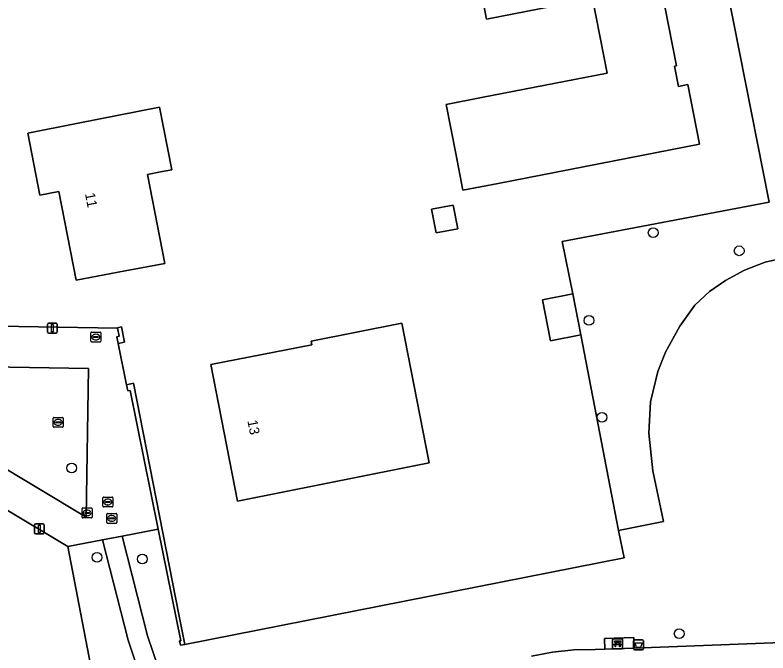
# Model space of a CAD drawing. Extents: x 157648 to 158502, y 379212 to 380938.
# Drawn here: x 158181.3 to 158256.8, y 380118.2 to 380182.1 of the extents above; entities that cross this region are included whole.
import ezdxf

# ---------------------------------------------------------------- set-up
doc = ezdxf.new("R2010")
doc.units = 0
for name, color, linetype in [('IMGEO_Afvalbak', 7, 'Continuous'), ('IMGEO_Bank', 7, 'Continuous'), ('IMGEO_Boom', 7, 'Continuous'), ('IMGEO_Brandkraan', 7, 'Continuous'), ('IMGEO_Erf', 7, 'Continuous'), ('IMGEO_Groenvoorziening', 7, 'Continuous'), ('IMGEO_Hek', 7, 'Continuous'), ('IMGEO_Kolk', 7, 'Continuous'), ('IMGEO_Lichtmast', 7, 'Continuous'), ('IMGEO_Muur', 7, 'Continuous'), ('IMGEO_Pand', 7, 'Continuous'), ('IMGEO_Pand_nummerreeks', 7, 'Continuous'), ('IMGEO_Rioolput', 7, 'Continuous'), ('IMGEO_Voetpad_halfverhard', 7, 'Continuous'), ('IMGEO_Voetpad_open', 7, 'Continuous')]:
    doc.layers.add(name, color=color, linetype=linetype)

msp = doc.modelspace()

# ---------------------------------------------------------------- linework, layer by layer
at = {"layer": 'IMGEO_Afvalbak'}
for p, q in [((158243.348, 380118.59), (158243.348, 380119.39)), ((158243.348, 380119.39), (158243.348, 380118.59)), ((158243.448, 380119.49), (158244.238, 380119.49)), ((158244.238, 380119.49), (158243.448, 380119.49)), ((158244.338, 380119.39), (158244.338, 380118.59)), ((158244.338, 380118.59), (158244.338, 380119.39)), ((158244.238, 380118.49), (158243.448, 380118.49)), ((158243.448, 380118.49), (158244.238, 380118.49))]:
    msp.add_line(p, q, dxfattribs=at)
msp.add_lwpolyline([(158243.491, 380119.204), (158244.195, 380119.204), (158244.046, 380118.734), (158243.64, 380118.734), (158243.491, 380119.204)], dxfattribs=at)
for centre, start, end in [((158243.448, 380119.39), 90, 180), ((158243.448, 380119.39), 90, 180), ((158244.238, 380119.39), 0, 90), ((158244.238, 380119.39), 360, 90), ((158243.448, 380118.59), 180, 270), ((158243.448, 380118.59), 180, 270), ((158244.238, 380118.59), 270, 0), ((158244.238, 380118.59), 270, 0)]:
    msp.add_arc(centre, 0.1, start, end, dxfattribs=at)
at = {"layer": 'IMGEO_Bank'}
for p, q in [((158241.312, 380119.603), (158242.153, 380119.603)), ((158242.153, 380119.603), (158241.312, 380119.603)), ((158241.237, 380118.678), (158241.237, 380119.519)), ((158241.237, 380119.519), (158241.237, 380118.678)), ((158241.934, 380119.001), (158241.541, 380119.001)), ((158241.546, 380119.109), (158241.546, 380119.215)), ((158241.59, 380119.215), (158241.59, 380119.109)), ((158241.878, 380119.221), (158241.596, 380119.221)), ((158241.596, 380119.103), (158241.878, 380119.103)), ((158241.884, 380119.109), (158241.884, 380119.215)), ((158241.928, 380119.215), (158241.928, 380119.109)), ((158242.237, 380119.528), (158242.237, 380118.687)), ((158242.237, 380118.687), (158242.237, 380119.528)), ((158242.162, 380118.603), (158241.321, 380118.603)), ((158241.321, 380118.603), (158242.162, 380118.603))]:
    msp.add_line(p, q, dxfattribs=at)
for points in [[(158241.484, 380119.001), (158241.342, 380119.001), (158241.454, 380119.103), (158241.54, 380119.103)], [(158241.54, 380119.221), (158241.454, 380119.221), (158241.454, 380119.382), (158242.017, 380119.382), (158242.017, 380119.221), (158241.934, 380119.221)], [(158241.534, 380118.994), (158241.534, 380118.787), (158241.491, 380118.787), (158241.491, 380118.994)], [(158241.934, 380119.103), (158242.017, 380119.103), (158242.129, 380119.001), (158241.99, 380119.001)], [(158241.984, 380118.994), (158241.984, 380118.787), (158241.94, 380118.787), (158241.94, 380118.994)]]:
    msp.add_lwpolyline(points, dxfattribs=at)
for centre, radius, start, end in [((158241.315, 380119.525), 0.0779, 92.4484, 184.28452), ((158241.315, 380119.525), 0.0779, 92.4484, 184.28452), ((158242.159, 380119.525), 0.0779, 2.4484, 94.28452), ((158242.159, 380119.525), 0.0779, 2.4484, 94.28452), ((158241.484, 380118.994), 0.00671, 2.89567, 87.10433), ((158241.541, 380118.994), 0.00671, 92.89567, 177.10433), ((158241.539, 380119.214), 0.00671, 2.89567, 87.10433), ((158241.539, 380119.11), 0.00671, 272.89567, 357.10433), ((158241.596, 380119.214), 0.00671, 92.89567, 177.10433), ((158241.596, 380119.11), 0.00671, 182.89567, 267.10433), ((158241.878, 380119.214), 0.00671, 2.89567, 87.10433), ((158241.878, 380119.11), 0.00671, 272.89567, 357.10433), ((158241.935, 380119.214), 0.00671, 92.89567, 177.10433), ((158241.935, 380119.11), 0.00671, 182.89567, 267.10433), ((158241.933, 380118.994), 0.00671, 2.89567, 87.10433), ((158241.99, 380118.994), 0.00671, 92.89567, 177.10433), ((158241.315, 380118.681), 0.0779, 182.4484, 274.28452), ((158241.315, 380118.681), 0.0779, 182.4484, 274.28452), ((158242.159, 380118.681), 0.0779, 272.4484, 4.28452), ((158242.159, 380118.681), 0.0779, 272.4484, 4.28452)]:
    msp.add_arc(centre, radius, start, end, dxfattribs=at)
at = {"layer": 'IMGEO_Boom'}
for centre in [(158245.306, 380160.323), (158253.93, 380158.505), (158238.865, 380151.522), (158240.182, 380141.801), (158187.008, 380136.719), (158189.549, 380127.768), (158194.086, 380127.603), (158247.912, 380120.113)]:
    msp.add_circle(centre, 0.489, dxfattribs=at)
at = {"layer": 'IMGEO_Brandkraan'}
for p, q in [((158188.929, 380149.431), (158188.929, 380150.283)), ((158189.004, 380150.357), (158189.856, 380150.357)), ((158189.188, 380149.851), (158189.188, 380149.863)), ((158189.626, 380149.814), (158189.228, 380149.814)), ((158189.231, 380149.9), (158189.629, 380149.9)), ((158189.417, 380150.137), (158189.442, 380150.137)), ((158189.672, 380149.863), (158189.672, 380149.851)), ((158189.93, 380150.283), (158189.93, 380149.431)), ((158189.856, 380149.357), (158189.004, 380149.357)), ((158189.44, 380149.577), (158189.415, 380149.577))]:
    msp.add_line(p, q, dxfattribs=at)
for points in [[(158188.929, 380149.431), (158188.929, 380150.283)], [(158189.004, 380150.357), (158189.856, 380150.357)], [(158189.93, 380150.283), (158189.93, 380149.431)], [(158189.856, 380149.357), (158189.004, 380149.357)]]:
    msp.add_lwpolyline(points, dxfattribs=at)
for centre, radius, start, end in [((158189.006, 380150.281), 0.0765, 91.55205, 178.44795), ((158189.006, 380150.281), 0.0765, 91.55205, 178.44795), ((158189.228, 380149.86), 0.0403, 85.87752, 175.75265), ((158189.225, 380149.85), 0.0366, 178.93798, 274.71019), ((158189.629, 380149.857), 0.043, 264.86636, 352.45326), ((158189.633, 380149.862), 0.0386, 1.73085, 96.63898), ((158189.854, 380150.281), 0.0765, 1.55205, 88.44795), ((158189.854, 380150.281), 0.0765, 1.55205, 88.44795), ((158189.006, 380149.433), 0.0765, 181.55205, 268.44795), ((158189.006, 380149.433), 0.0765, 181.55205, 268.44795), ((158189.854, 380149.433), 0.0765, 271.55205, 358.44795), ((158189.854, 380149.433), 0.0765, 271.55205, 358.44795)]:
    msp.add_arc(centre, radius, start, end, dxfattribs=at)
for centre, major_axis, ratio, start_param, end_param in [((158189.416, 380149.857), (-0.387, 0.002), 0.722429, 4.712389, 7.853982), ((158189.441, 380149.857), (-0.39, 0.002), 0.717154, 1.570796, 4.712389)]:
    msp.add_ellipse(centre, major_axis=major_axis, ratio=ratio, start_param=start_param, end_param=end_param, dxfattribs=at)
at = {"layer": 'IMGEO_Erf'}
for points in [[(158253.955, 380178.433), (158249.732, 380199.752), (158249.31, 380199.723), (158249.282, 380199.871), (158225.953, 380195.277), (158226.014, 380194.869), (158222.575, 380194.188), (158222.466, 380194.594), (158221.97, 380194.353), (158214.817, 380209.454), (158195.034, 380205.584)], [(158175.95, 380186.37), (158171.741, 380151.076), (158191.586, 380150.755), (158191.589, 380150.781), (158191.991, 380150.866), (158192.313, 380149.335), (158191.672, 380149.199), (158192.511, 380145.079), (158193.188, 380145.224), (158197.79, 380121.862), (158198.344, 380119.047), (158242.386, 380127.715), (158241.844, 380130.469), (158238.043, 380150.085), (158235.002, 380149.49), (158234.201, 380153.591), (158237.242, 380154.185), (158236.166, 380159.436), (158256.938, 380163.375), (158253.955, 380178.433)], [(158124.564, 379960.342), (158206.82, 380026.58), (158196.915, 380075.272), (158189.705, 380112.851), (158186.635, 380128.853), (158166.68, 380140.8), (158143.542, 380114.501)]]:
    msp.add_lwpolyline(points, dxfattribs=at)
for points in [[(158226.941, 380190.21), (158245.144, 380193.768), (158246.103, 380188.861), (158246.816, 380185.212), (158246.089, 380185.07), (158247.655, 380177.059), (158247.432, 380177.014), (158247.828, 380174.987), (158248.778, 380175.171), (158249.944, 380169.206), (158229.771, 380165.263), (158226.238, 380164.572), (158225.516, 380168.269), (158224.557, 380173.176), (158228.089, 380173.866), (158240.698, 380176.33), (158239.234, 380183.819), (158228.596, 380181.74)], [(158196.329, 380157.237), (158192.368, 380156.509), (158187.461, 380155.55), (158185.719, 380164.464), (158183.81, 380164.091), (158182.594, 380170.311), (158187.502, 380171.27), (158195.819, 380172.895), (158197.042, 380166.633), (158195.895, 380166.409), (158194.593, 380166.154)], [(158225.726, 380160.723), (158223.556, 380160.299), (158223.092, 380162.669), (158225.262, 380163.093)], [(158220.104, 380151.233), (158222.836, 380137.254), (158203.619, 380133.389), (158200.948, 380147.111), (158211.076, 380149.09), (158211.005, 380149.455)]]:
    msp.add_lwpolyline(points, close=True, dxfattribs=at)
at = {"layer": 'IMGEO_Groenvoorziening'}
for points in [[(158249.732, 380199.752), (158253.955, 380178.433), (158256.938, 380163.375), (158236.166, 380159.436), (158237.242, 380154.185), (158238.043, 380150.085), (158241.844, 380130.469), (158246.34, 380131.354), (158245.283, 380136.444), (158244.881, 380140.214), (158245.051, 380143.35), (158245.768, 380146.398), (158246.55, 380148.355), (158247.991, 380150.961), (158249.472, 380153.047), (158250.941, 380154.422), (158252.551, 380155.518), (158254.465, 380156.577), (158256.52, 380157.382), (158258.436, 380157.793)], [(158258.436, 380157.793), (158256.52, 380157.382), (158254.465, 380156.577), (158252.551, 380155.518), (158250.941, 380154.422), (158249.472, 380153.047), (158247.991, 380150.961), (158246.55, 380148.355), (158245.768, 380146.398), (158245.051, 380143.35), (158244.881, 380140.214), (158245.283, 380136.444), (158246.34, 380131.354), (158241.844, 380130.469), (158242.386, 380127.715), (158198.344, 380119.047), (158197.914, 380118.959), (158197.828, 380119.391), (158197.936, 380119.413), (158195.683, 380130.589), (158192.06, 380129.894), (158194.594, 380119.898), (158197.853, 380110.36)], [(158195.848, 380109.962), (158192.652, 380119.474), (158190.09, 380129.516), (158186.635, 380128.853), (158189.705, 380112.851)], [(158233.093, 380117.862), (158235.206, 380118.271), (158237.346, 380118.49), (158239.497, 380118.517), (158240.456, 380118.552), (158240.415, 380119.62), (158243.358, 380119.734), (158243.399, 380118.667), (158265.976, 380119.538)]]:
    msp.add_lwpolyline(points, dxfattribs=at)
at = {"layer": 'IMGEO_Hek'}
msp.add_lwpolyline([(158241.844, 380130.469), (158242.386, 380127.715), (158198.344, 380119.047)], dxfattribs=at)
at = {"layer": 'IMGEO_Kolk'}
for p, q in [((158185.148, 380140.88), (158185.148, 380141.732)), ((158185.223, 380141.806), (158186.075, 380141.806)), ((158185.636, 380141.586), (158185.661, 380141.586)), ((158186.149, 380141.732), (158186.149, 380140.88)), ((158186.075, 380140.806), (158185.223, 380140.806)), ((158185.407, 380141.3), (158185.407, 380141.312)), ((158185.845, 380141.263), (158185.447, 380141.263)), ((158185.45, 380141.349), (158185.848, 380141.349)), ((158185.659, 380141.026), (158185.634, 380141.026)), ((158185.891, 380141.312), (158185.891, 380141.3))]:
    msp.add_line(p, q, dxfattribs=at)
for points in [[(158185.148, 380140.88), (158185.148, 380141.732)], [(158185.223, 380141.806), (158186.075, 380141.806)], [(158186.149, 380141.732), (158186.149, 380140.88)], [(158186.075, 380140.806), (158185.223, 380140.806)]]:
    msp.add_lwpolyline(points, dxfattribs=at)
for centre, radius, start, end in [((158185.225, 380141.73), 0.0765, 91.55205, 178.44795), ((158185.225, 380141.73), 0.0765, 91.55205, 178.44795), ((158186.073, 380141.73), 0.0765, 1.55205, 88.44795), ((158186.073, 380141.73), 0.0765, 1.55205, 88.44795), ((158185.225, 380140.882), 0.0765, 181.55205, 268.44795), ((158185.225, 380140.882), 0.0765, 181.55205, 268.44795), ((158185.447, 380141.309), 0.0403, 85.87752, 175.75265), ((158185.444, 380141.299), 0.0366, 178.93798, 274.71019), ((158185.848, 380141.306), 0.043, 264.86636, 352.45326), ((158185.852, 380141.311), 0.0386, 1.73085, 96.63898), ((158186.073, 380140.882), 0.0765, 271.55205, 358.44795), ((158186.073, 380140.882), 0.0765, 271.55205, 358.44795)]:
    msp.add_arc(centre, radius, start, end, dxfattribs=at)
for centre, major_axis, ratio, start_param, end_param in [((158185.635, 380141.306), (-0.387, 0.002), 0.722429, 4.712389, 7.853982), ((158185.66, 380141.306), (-0.39, 0.002), 0.717154, 1.570796, 4.712389)]:
    msp.add_ellipse(centre, major_axis=major_axis, ratio=ratio, start_param=start_param, end_param=end_param, dxfattribs=at)
at = {"layer": 'IMGEO_Lichtmast'}
for p, q in [((158184.57, 380150.35), (158184.57, 380151.15)), ((158184.57, 380151.15), (158184.57, 380150.35)), ((158184.67, 380151.25), (158185.46, 380151.25)), ((158185.46, 380151.25), (158184.67, 380151.25)), ((158185.56, 380151.15), (158185.56, 380150.35)), ((158185.56, 380150.35), (158185.56, 380151.15)), ((158185.46, 380150.25), (158184.67, 380150.25)), ((158184.67, 380150.25), (158185.46, 380150.25)), ((158183.263, 380130.231), (158183.263, 380131.031)), ((158183.263, 380131.031), (158183.263, 380130.231)), ((158183.363, 380131.131), (158184.153, 380131.131)), ((158184.153, 380131.131), (158183.363, 380131.131)), ((158184.253, 380131.031), (158184.253, 380130.231)), ((158184.253, 380130.231), (158184.253, 380131.031)), ((158184.153, 380130.131), (158183.363, 380130.131)), ((158183.363, 380130.131), (158184.153, 380130.131))]:
    msp.add_line(p, q, dxfattribs=at)
for points in [[(158184.99, 380151.125), (158185.14, 380151.125), (158185.14, 380150.375), (158184.99, 380150.375), (158184.99, 380151.125)], [(158183.683, 380131.006), (158183.833, 380131.006), (158183.833, 380130.256), (158183.683, 380130.256), (158183.683, 380131.006)]]:
    msp.add_lwpolyline(points, dxfattribs=at)
for centre, start, end in [((158184.67, 380151.15), 90, 180), ((158184.67, 380151.15), 90, 180), ((158185.46, 380151.15), 0, 90), ((158185.46, 380151.15), 360, 90), ((158184.67, 380150.35), 180, 270), ((158184.67, 380150.35), 180, 270), ((158185.46, 380150.35), 270, 0), ((158185.46, 380150.35), 270, 0), ((158183.363, 380131.031), 90, 180), ((158183.363, 380131.031), 90, 180), ((158184.153, 380131.031), 0, 90), ((158184.153, 380131.031), 360, 90), ((158183.363, 380130.231), 180, 270), ((158183.363, 380130.231), 180, 270), ((158184.153, 380130.231), 270, 0), ((158184.153, 380130.231), 270, 0)]:
    msp.add_arc(centre, 0.1, start, end, dxfattribs=at)
at = {"layer": 'IMGEO_Muur'}
for points in [[(158191.991, 380150.866), (158191.589, 380150.781), (158191.586, 380150.755), (158191.75, 380149.937), (158191.532, 380149.884), (158191.672, 380149.199), (158192.313, 380149.335)], [(158193.188, 380145.224), (158192.511, 380145.079), (158192.638, 380144.456), (158192.864, 380144.491), (158195.683, 380130.589), (158197.936, 380119.413), (158197.828, 380119.391), (158197.914, 380118.959), (158198.344, 380119.047), (158197.79, 380121.862)]]:
    msp.add_lwpolyline(points, close=True, dxfattribs=at)
at = {"layer": 'IMGEO_Pand'}
for points in [[(158246.103, 380188.861), (158245.144, 380193.768), (158226.941, 380190.21), (158228.596, 380181.74), (158239.234, 380183.819), (158240.698, 380176.33), (158228.089, 380173.866), (158224.557, 380173.176), (158225.516, 380168.269), (158226.238, 380164.572), (158229.771, 380165.263), (158249.944, 380169.206), (158248.778, 380175.171), (158247.828, 380174.987), (158247.432, 380177.014), (158247.655, 380177.059), (158246.089, 380185.07), (158246.816, 380185.212)], [(158192.368, 380156.509), (158196.329, 380157.237), (158194.593, 380166.154), (158195.895, 380166.409), (158197.042, 380166.633), (158195.819, 380172.895), (158187.502, 380171.27), (158182.594, 380170.311), (158183.81, 380164.091), (158185.719, 380164.464), (158187.461, 380155.55)], [(158225.726, 380160.723), (158225.262, 380163.093), (158223.092, 380162.669), (158223.556, 380160.299)], [(158237.242, 380154.185), (158234.201, 380153.591), (158235.002, 380149.49), (158238.043, 380150.085)], [(158200.948, 380147.111), (158203.619, 380133.389), (158222.836, 380137.254), (158220.104, 380151.233), (158211.005, 380149.455), (158211.076, 380149.09)]]:
    msp.add_lwpolyline(points, close=True, dxfattribs=at)
at = {"layer": 'IMGEO_Rioolput'}
for p, q in [((158190.127, 380132.893), (158190.127, 380133.745)), ((158190.202, 380133.819), (158191.054, 380133.819)), ((158190.386, 380133.313), (158190.386, 380133.325)), ((158190.824, 380133.276), (158190.426, 380133.276)), ((158190.429, 380133.362), (158190.827, 380133.362)), ((158190.615, 380133.599), (158190.64, 380133.599)), ((158190.87, 380133.325), (158190.87, 380133.313)), ((158191.128, 380133.745), (158191.128, 380132.893)), ((158188.05, 380131.796), (158188.05, 380132.648)), ((158188.125, 380132.722), (158188.977, 380132.722)), ((158188.538, 380132.502), (158188.563, 380132.502)), ((158189.051, 380132.648), (158189.051, 380131.796)), ((158191.054, 380132.819), (158190.202, 380132.819)), ((158190.638, 380133.039), (158190.613, 380133.039)), ((158188.977, 380131.722), (158188.125, 380131.722)), ((158188.309, 380132.216), (158188.309, 380132.228)), ((158188.747, 380132.179), (158188.349, 380132.179)), ((158188.352, 380132.265), (158188.75, 380132.265)), ((158188.561, 380131.942), (158188.536, 380131.942)), ((158188.793, 380132.228), (158188.793, 380132.216)), ((158190.525, 380131.252), (158190.525, 380132.104)), ((158190.6, 380132.178), (158191.452, 380132.178)), ((158190.784, 380131.672), (158190.784, 380131.684)), ((158190.827, 380131.721), (158191.225, 380131.721)), ((158191.013, 380131.958), (158191.038, 380131.958)), ((158191.268, 380131.684), (158191.268, 380131.672)), ((158191.526, 380132.104), (158191.526, 380131.252)), ((158191.452, 380131.178), (158190.6, 380131.178)), ((158191.222, 380131.635), (158190.824, 380131.635)), ((158191.036, 380131.398), (158191.011, 380131.398))]:
    msp.add_line(p, q, dxfattribs=at)
for points in [[(158190.127, 380132.893), (158190.127, 380133.745)], [(158190.202, 380133.819), (158191.054, 380133.819)], [(158191.128, 380133.745), (158191.128, 380132.893)], [(158188.05, 380131.796), (158188.05, 380132.648)], [(158188.125, 380132.722), (158188.977, 380132.722)], [(158189.051, 380132.648), (158189.051, 380131.796)], [(158191.054, 380132.819), (158190.202, 380132.819)], [(158188.977, 380131.722), (158188.125, 380131.722)], [(158190.525, 380131.252), (158190.525, 380132.104)], [(158190.6, 380132.178), (158191.452, 380132.178)], [(158191.526, 380132.104), (158191.526, 380131.252)], [(158191.452, 380131.178), (158190.6, 380131.178)]]:
    msp.add_lwpolyline(points, dxfattribs=at)
for centre, radius, start, end in [((158190.204, 380133.743), 0.0765, 91.55205, 178.44795), ((158190.204, 380133.743), 0.0765, 91.55205, 178.44795), ((158190.426, 380133.322), 0.0403, 85.87752, 175.75265), ((158190.423, 380133.312), 0.0366, 178.93798, 274.71019), ((158190.827, 380133.319), 0.043, 264.86636, 352.45326), ((158190.831, 380133.324), 0.0386, 1.73085, 96.63898), ((158191.052, 380133.743), 0.0765, 1.55205, 88.44795), ((158191.052, 380133.743), 0.0765, 1.55205, 88.44795), ((158188.127, 380132.646), 0.0765, 91.55205, 178.44795), ((158188.127, 380132.646), 0.0765, 91.55205, 178.44795), ((158188.975, 380132.646), 0.0765, 1.55205, 88.44795), ((158188.975, 380132.646), 0.0765, 1.55205, 88.44795), ((158190.204, 380132.895), 0.0765, 181.55205, 268.44795), ((158190.204, 380132.895), 0.0765, 181.55205, 268.44795), ((158191.052, 380132.895), 0.0765, 271.55205, 358.44795), ((158191.052, 380132.895), 0.0765, 271.55205, 358.44795), ((158188.127, 380131.798), 0.0765, 181.55205, 268.44795), ((158188.127, 380131.798), 0.0765, 181.55205, 268.44795), ((158188.349, 380132.225), 0.0403, 85.87752, 175.75265), ((158188.346, 380132.215), 0.0366, 178.93798, 274.71019), ((158188.75, 380132.222), 0.043, 264.86636, 352.45326), ((158188.754, 380132.227), 0.0386, 1.73085, 96.63898), ((158188.975, 380131.798), 0.0765, 271.55205, 358.44795), ((158188.975, 380131.798), 0.0765, 271.55205, 358.44795), ((158190.602, 380132.102), 0.0765, 91.55205, 178.44795), ((158190.602, 380132.102), 0.0765, 91.55205, 178.44795), ((158190.824, 380131.681), 0.0403, 85.87752, 175.75265), ((158191.229, 380131.683), 0.0386, 1.73085, 96.63898), ((158191.45, 380132.102), 0.0765, 1.55205, 88.44795), ((158191.45, 380132.102), 0.0765, 1.55205, 88.44795), ((158190.602, 380131.254), 0.0765, 181.55205, 268.44795), ((158190.602, 380131.254), 0.0765, 181.55205, 268.44795), ((158190.821, 380131.671), 0.0366, 178.93798, 274.71019), ((158191.225, 380131.678), 0.043, 264.86636, 352.45326), ((158191.45, 380131.254), 0.0765, 271.55205, 358.44795), ((158191.45, 380131.254), 0.0765, 271.55205, 358.44795)]:
    msp.add_arc(centre, radius, start, end, dxfattribs=at)
for centre, major_axis, ratio, start_param, end_param in [((158190.614, 380133.319), (-0.387, 0.002), 0.722429, 4.712389, 7.853982), ((158190.639, 380133.319), (-0.39, 0.002), 0.717154, 1.570796, 4.712389), ((158188.537, 380132.222), (-0.387, 0.002), 0.722429, 4.712389, 7.853982), ((158188.562, 380132.222), (-0.39, 0.002), 0.717154, 1.570796, 4.712389), ((158191.012, 380131.678), (-0.387, 0.002), 0.722429, 4.712389, 7.853982), ((158191.037, 380131.678), (-0.39, 0.002), 0.717154, 1.570796, 4.712389)]:
    msp.add_ellipse(centre, major_axis=major_axis, ratio=ratio, start_param=start_param, end_param=end_param, dxfattribs=at)
at = {"layer": 'IMGEO_Voetpad_halfverhard'}
for points in [[(158197.853, 380110.36), (158194.594, 380119.898), (158192.06, 380129.894), (158190.09, 380129.516), (158192.652, 380119.474), (158195.848, 380109.962)], [(158265.976, 380119.538), (158243.399, 380118.667), (158240.456, 380118.552), (158239.497, 380118.517), (158237.346, 380118.49), (158235.206, 380118.271), (158233.093, 380117.862)]]:
    msp.add_lwpolyline(points, dxfattribs=at)
at = {"layer": 'IMGEO_Voetpad_open'}
for points in [[(158191.672, 380149.199), (158191.532, 380149.884), (158191.75, 380149.937), (158191.586, 380150.755), (158171.741, 380151.076), (158170.949, 380147.011), (158188.691, 380146.709), (158188.471, 380131.813), (158168.979, 380143.487), (158166.68, 380140.8), (158186.635, 380128.853), (158190.09, 380129.516), (158192.06, 380129.894), (158195.683, 380130.589), (158192.864, 380144.491), (158192.638, 380144.456), (158192.511, 380145.079)], [(158170.949, 380147.011), (158168.979, 380143.487), (158188.471, 380131.813), (158188.691, 380146.709)], [(158243.399, 380118.667), (158243.358, 380119.734), (158240.415, 380119.62), (158240.456, 380118.552)]]:
    msp.add_lwpolyline(points, close=True, dxfattribs=at)

# ---------------------------------------------------------------- texts
at = {"layer": 'IMGEO_Pand_nummerreeks'}
for s, rotation, p in [('11', 281.05755, (158188.333, 380164.227)), ('13', 281.01202, (158204.617, 380141.453))]:
    msp.add_text(s, height=1, rotation=rotation, dxfattribs=at).set_placement(p)

doc.saveas('drawing.dxf')
